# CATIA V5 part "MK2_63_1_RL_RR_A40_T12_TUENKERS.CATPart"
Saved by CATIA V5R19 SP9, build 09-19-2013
Part number: MK2_63_1_RL_RR_A40_T12_TUENKERS
Material "MISCHDICHTE": density 4951.5 kg/m3, Young's modulus 2e+11 Pa, Poisson ratio 0.266
Bounding box of the stored display mesh (mm): x -193.5 to 144, y -121.5 to 73, z -122.161 to 122.161
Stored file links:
  G:\Konstruktion\Modelle\Catia_V5\MK2_63_1_RL_RR_A40_T12_TUENKERS.CATPart
  G:\Konstruktion\Modelle\Catia_V5\Spannarme\SPANNARM_KPL_63_A10_217498_TUENKERS.CATPart
  C:\Catia\Tuenkers_B19SP9HF86_64\win_b64\reffiles\standard\MetricThickPitch.txt
  G:\Konstruktion\Modelle\Catia_V5\Spannarme\SPANNARM_KPL_63_A40_242839_TUENKERS.CATPart
  G:\Konstruktion\Modelle\Catia_V5\MK_63_1_A10_T12_TUENKERS.CATPart
  G:\Konstruktion\Modelle\Catia_V5\V2_63_1_BR3_ZL_ZR_RL_RR_A40_T12_TUENKERS.CATPart
  HANDHEBEL_KPL_50_63_TUENKERS.CATPart
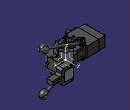
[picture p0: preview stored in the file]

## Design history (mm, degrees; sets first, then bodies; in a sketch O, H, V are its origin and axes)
AxisSystem1: origin (0, 0, 0), X (1, 0, 0), Y (0, 1, 0), Z (0, 0, 1)
Body1 (main body)
  Body2 "*DIT1\\*DIT2\\"
    Solid1: solid without history
  Assemble1: tool Body2
  Body3 "*DIT1\\*DIT3"
    Solid2 "Solid.1": solid without history
  Assemble2: tool Body3
  Body4 "*DIT1\\*DIT12\\*DIT16\\"
    Solid3 "Solid.1": solid without history
  Assemble3: tool Body4
  Body5 "*DIT1\\*DIT12\\*DIT17\\"
    Solid4 "Solid.1": solid without history
  Assemble4: tool Body5
  Body6 "*DIT1\\*DIT12\\MK_MK2_63_1_A10_A11_A12_T12_081112_3D_xSET4_2.1"
    Solid5 "Solid.1": solid without history
    Body7 "*DIT1\\*DIT12\\MK_MK2_63_1_A10_A11_A12_T12_081112_3D_xSET4_2.1\\Body.11 ( *SOL16 - wsp GEHAEUSE -  )"
      Solid6 "Solid.1": solid without history
    Add1 "*DIT1\\*DIT12\\MK_MK2_63_1_A10_A11_A12_T12_081112_3D_xSET4_2.1\\Body.11 ( *SOL16 - wsp GEHAEUSE -  )": tool Body7
    Body8 "*DIT1\\*DIT12\\MK_MK2_63_1_A10_A11_A12_T12_081112_3D_xSET4_2.1\\Body.12 ( *SOL17 - wsp GEHAEUSE -  )"
      Solid7 "Solid.1": solid without history
    Add2 "*DIT1\\*DIT12\\MK_MK2_63_1_A10_A11_A12_T12_081112_3D_xSET4_2.1\\Body.12 ( *SOL17 - wsp GEHAEUSE -  )": tool Body8
    Body9 "*DIT1\\*DIT12\\MK_MK2_63_1_A10_A11_A12_T12_081112_3D_xSET4_2.1\\Body.14 ( *SOL18 - wsp GEHAEUSE -  )"
      Solid8 "Solid.1": solid without history
    Add3 "*DIT1\\*DIT12\\MK_MK2_63_1_A10_A11_A12_T12_081112_3D_xSET4_2.1\\Body.14 ( *SOL18 - wsp GEHAEUSE -  )": tool Body9
  Assemble5: tool Body6
  Body10 "*DIT1\\MK_MK2_63_1_A10_A11_A12_T12_081112_3D_xSET2_1.1"
    Solid9 "Solid.1": solid without history
  Assemble6: tool Body10
  Rotate1: Axis edge [XY plane of AxisSystem1 | ZX plane of AxisSystem1], Angle 90, ToTransfor Assemble6
  Body11
    Body12 "*DIT1\\MK_MK2_63_1_A10_A11_A12_T12_081112_3D_xSET2_1.1\\Body.2 ( *SOL2 - wsp MK_MK2 63_1 -  )"
      Solid10 "Solid.1": solid without history
    Assemble7: tool Body12
    Body13 "*DIT1\\MK_MK2_63_1_A10_A11_A12_T12_081112_3D_xSET2_1.1\\Body.3 ( *SOL3 - wsp MK_MK2 63_1 -  )"
      Solid11 "Solid.1": solid without history
    Assemble8: tool Body13
    Body14 "*DIT1\\MK_MK2_63_1_A10_A11_A12_T12_081112_3D_xSET2_1.1\\Body.4 ( *SOL4 - wsp MK_MK2 63_1 -  )"
      Solid12 "Solid.1": solid without history
    Assemble9: tool Body14
    Body15 "*DIT1\\MK_MK2_63_1_A10_A11_A12_T12_081112_3D_xSET2_1.1\\Body.5 ( *SOL5 - wsp MK_MK2 63_1 -  )"
      Solid13 "Solid.1": solid without history
    Assemble10: tool Body15
    Body16 "*DIT1\\MK_MK2_63_1_A10_A11_A12_T12_081112_3D_xSET2_1.1\\Body.6 ( *SOL6 - wsp MK_MK2 63_1 -  )"
      Solid14 "Solid.1": solid without history
    Assemble11: tool Body16
    Rotate2: Axis edge, Angle 90, ToTransfor Assemble11
    Translate1: Direction edge [YZ plane of AxisSystem1 | XY plane of AxisSystem1], Length -1, ToTransfor Rotate2
  Assemble12: tool Body11
Body17 "Spannarm_kpl_63_A40_242839_Tuenkers", material "Steel"
  Sketch1 on xy-plane, origin (0, 0, 0), H (1, 0, 0), V (0, 1, 0)
    line L1 (73, 144) -> (45, 144)
    arc A1 centre (53, 43.1005) radius 20 from (67.1421, 28.9584) to (73, 43.1005) ccw
    line L2 (67.1421, 28.9584) -> (19.0919, -19.0919)
    line L3 (10.9602, 10.9602) -> (10.9602, -10.9602)
    line L4 (10.9602, 10.9602) -> (-10.9602, 10.9602)
    line L5 (-19.0919, 19.0919) -> (-10.9602, 10.9602)
    line L6 (-1.4396, 36.7442) -> (-19.0919, 19.0919)
    line L7 (38.4202, 51.252) -> (-1.4396, 36.7442)
    arc A2 centre (35, 60.6489) radius 10 from (38.4202, 51.252) to (45, 60.6489) ccw
    line L8 (45, 60.6489) -> (45, 144)
    line L9 (73, 144) -> (73, 43.1005)
    line L10 (10.9602, -10.9602) -> (19.0919, -19.0919)
    point P7 (10.9602, 10.9602)
    point P10 (-1.4396, 36.7442)
    point P13 (73, 37.6447)
    point P14 (45, 51.7188)
    reference intersected line E1 through (0, 0) direction (-0.7071, 0.7071)
    reference intersected line E2 through (0, 0) direction (-0.7071, 0.7071)
    reference intersected line E3 through (0, 0) direction (-0.7071, 0.7071)
    reference intersected line E4 through (0, 0) direction (0, 1) from yz-plane
    reference intersected line E5 through (0, 0) direction (-1, 0) from zx-plane
    reference intersected line E6 through (0, 0) direction (0, 1) from yz-plane
    angle L6 L7 = 25
    radius A1 = 20
    angle L4 L5 = 45
    distance P7 L2 = 27
    distance L2 L6 = 54
    angle L2 L10 = 90
    distance P7 E1 = 15.5
    distance E4 L3 = 10.9602
    distance E5 L1 = 144
    distance E6 L8 = 45
    distance L9 L8 = 28
    radius A2 = 10
    distance P10 L1 = 107.2558
    tangency: A1 L2, L8 A2, A2 L7, L9 A1
    coincidence: L10 E2, L5 E3
  Pad1: profile Sketch1, direction (0, 0, 1), length 39, opposite side length 39
  Chamfer1: length 0.1, angle 45, on edge [face of Pad1 from Sketch1.L3 | end face of Pad1]; edge [face of Pad1 from Sketch1.L4 | end face of Pad1]; edge [start face of Pad1 | face of Pad1 from Sketch1.L4]; edge [start face of Pad1 | face of Pad1 from Sketch1.L3]
  Sketch2 on face of Pad1 from Sketch1.L9, origin (73, 0, 0), H (0, 1, 0), V (0, 0, 1)
    line L1 (144, -10) -> (144, 10)
    line L2 (103, 10) -> (144, 10)
    arc A1 centre (103, 18) radius 8 from (103, 10) to (95, 18) cw
    line L3 (95, 18) -> (95, 29)
    arc A2 centre (85, 29) radius 10 from (85, 39) to (95, 29) cw
    line L4 (-20, 39) -> (85, 39)
    line L5 (-20, 39) -> (-20, 27)
    line L6 (74, 27) -> (-20, 27)
    arc A3 centre (74, 21) radius 6 from (74, 27) to (80, 21) cw
    line L7 (80, 21) -> (80, -21)
    arc A4 centre (74, -21) radius 6 from (80, -21) to (74, -27) cw
    line L8 (-20, -27) -> (74, -27)
    line L9 (-20, -27) -> (-20, -39)
    line L10 (-20, -39) -> (85, -39)
    arc A5 centre (85, -29) radius 10 from (95, -29) to (85, -39) cw
    line L11 (95, -29) -> (95, -18)
    arc A6 centre (103, -18) radius 8 from (95, -18) to (103, -10) cw
    line L12 (103, -10) -> (144, -10)
    reference intersected line E1 through (0, 0) direction (-1, 0) from xy-plane
    reference intersected line E2 through (0, 0) direction (0, 1) from zx-plane
    reference intersected line E3 through (0, 0) direction (0, 1) from zx-plane
    reference intersected line E4 through (0, 0) direction (0, 1) from zx-plane
    line L13 (-30, -44) -> (160, -44)
    line L14 (160, -44) -> (160, 44)
    line L15 (160, 44) -> (-30, 44)
    line L16 (-30, 44) -> (-30, -44)
    reference intersected line E5 through (0, 0) direction (-1, 0) from xy-plane
    reference intersected line E6 through (0, 0) direction (0, 1) from zx-plane
    distance L12 E1 = 10
    distance L12 L2 = 20
    distance L4 L10 = 78
    distance L6 L8 = 54
    distance L10 L12 = 29
    distance L8 L10 = 12
    radius A3 = 6
    radius A4 = 6
    radius A5 = 10
    radius A2 = 10
    radius A1 = 8
    radius A6 = 8
    distance L7 E2 = 80
    distance L3 E3 = 95
    distance L1 L5 = 164
    distance E4 L1 = 144
    distance L16 L14 = 190
    distance L15 L13 = 88
    distance L13 E5 = 44
    distance L14 E6 = 160
    tangency: L6 A3, A3 L7, L7 A4, A4 L8, L10 A5, A5 L11, L3 A1, A1 L2, A6 L12, A2 L4, A2 L3, A6 L11
    vertical: L1 V, L14 V, L16 V
    horizontal: L12 H, L13 H, L15 H
    coincidence: L5 L9, L11 L3
  Pocket1: profile Sketch2, direction (-1, 0, 0), length 95
  Sketch3 on face of Pad1 from Sketch1.L9, origin (73, 131.0889, -0.3784), H (0, 1, 0), V (0, 0, 1)
    point P1 (3.9111, 0.3784)
    reference intersected line E1 through (0, 0.3784) direction (-1, 0) from xy-plane
    reference intersected line E2 through (-131.0889, 0) direction (0, 1) from zx-plane
    reference intersected line E3 through (-131.0889, 0) direction (0, 1) from zx-plane
    reference intersected line E4 (12.9111, -38.6216) -> (-87.9884, -38.6216) from start face of Pad1
    distance P1 E2 = 135
    distance E3 E4 = 0
    coincidence: P1 E1
  Hole1: placed by Sketch3, at (73, 135, 0) direction (-1, 0, 0), diameter 6, through (limit type 6)
  Sketch4 on face of Pad1 from Sketch1.L9, origin (73, 113.9529, 0.5693), H (0, 1, 0), V (0, 0, 1)
    point P1 (-8.9529, -0.5693)
    reference projected point E1 (21.0471, -0.5693) from axis of face of Hole1
    reference intersected line E2 through (0, -0.5693) direction (-1, 0) from xy-plane
    distance P1 E1 = 30
    coincidence: P1 E2
  Hole2: placed by Sketch4, at (73, 105, 0) direction (-1, 0, 0), diameter 6, through (limit type 6)
  Sketch5 on face of Pad1 from Sketch1.L9, origin (73, 123.4122, -0.1089), H (0, 1, 0), V (0, 0, 1)
    point P1 (-3.4122, 0.1089)
    reference projected point E1 (11.5878, 0.1089) from axis of face of Hole1
    reference projected point E2 (-18.4122, 0.1089) from axis of face of Hole2
    distance P1 E1 = 15
    distance E2 P1 = 15
  Hole3: placed by Sketch5, at (73, 120, 0) direction (-1, 0, 0), diameter 9, through (limit type 6)
  Sketch6 on face of Pad1 from Sketch1.L9, origin (73, 93.5248, 1.4062), H (0, 1, 0), V (0, 0, 1)
    point P1 (-3.5248, -1.4062)
    reference projected point E1 (26.4752, -1.4062) from axis of face of Hole3
    reference projected point E2 (11.4752, -1.4062) from axis of face of Hole2
    distance P1 E1 = 30
    distance P1 E2 = 15
  Hole4: placed by Sketch6, at (73, 90, 0) direction (-1, 0, 0), diameter 9, through (limit type 6)
  Sketch7 on face of Pad1 from Sketch1.L10, origin (13.7879, -13.7879, 28.7565), H (0.7071, -0.7071, 0), V (0, 0, 1)
    point P1 (0.5009, 4.2435)
    reference intersected line E1 through (0, -28.7565) direction (-1, 0) from xy-plane
    reference projected line E2 (-19.4991, -67.7565) -> (-19.4991, 10.2435) from edge [face of Pad1 from Sketch1.L3 | face of Pad1 from Sketch1.L4]
    distance P1 E1 = 33
    distance E2 P1 = 20
  Hole5: placed by Sketch7, at (14.1421, -14.1421, 33) direction (0.7071, 0.7071, 0), diameter 6.647, depth 18, V-bottom angle 120, threaded "M8", thread diameter 8, thread depth 15, pitch 1.25
  RectPattern1: of Hole5, direction 1 instances 2, spacing 66, along edge [face of Pad1 from Sketch1.L3 | face of Pad1 from Sketch1.L4] reversed, direction 2 instances 2, spacing 40, along edge [face of Pad1 from Sketch1.L10 | face of Pocket1] reversed
  Body18 "KLEMMFLANSCH KPL"
    Sketch8 on xy-plane, origin (0, 0, 0), H (1, 0, 0), V (0, 1, 0)
      line L1 (-20.5061, 17.6777) -> (-31.1375, 7.0463)
      line L2 (-31.1375, 7.0463) -> (-19.1167, -4.9745)
      line L3 (-19.1167, -4.9745) -> (-25.4806, -11.3385)
      line L4 (-25.4806, -11.3385) -> (-11.3385, -25.4806)
      line L5 (-11.3385, -25.4806) -> (-4.9745, -19.1167)
      line L6 (-4.9745, -19.1167) -> (7.0463, -31.1375)
      line L7 (7.0463, -31.1375) -> (19.0671, -19.1167)
      line L8 (19.0671, -19.1167) -> (10.9106, -10.9602)
      line L9 (10.9106, -10.9602) -> (-10.9602, -10.9602)
      point P10 (-10.9602, -10.9602)
      line L10 (-10.9602, -10.9602) -> (-10.9602, 8.1317)
      line L11 (-10.9602, 8.1317) -> (-20.5061, 17.6777)
      reference intersected line E1 through (0, 0) direction (-0.7071, 0.7071)
      reference intersected line E2 through (0, 0) direction (-0.7071, 0.7071)
      reference intersected line E3 through (0, 0) direction (-0.7071, -0.7071)
      distance L4 L8 = 26
      distance L7 L5 = 17
      distance L5 L3 = 20
      distance L7 L1 = 54
      distance L4 L6 = 9
      distance E1 P10 = 15.5
      distance L11 E2 = 2
      distance L11 L8 = 1.965
      angle L11 L10 = 135
      angle L9 L8 = 45
      distance L7 P10 = 27
      distance E3 L7 = 27
      coincidence: L2 L6
    Pad2: profile Sketch8, direction (0, 0, 1), length 39, opposite side length -27
    Chamfer2: length 0.1, angle 45, on edge [face of Pad2 from Sketch8.L9 | end face of Pad2]; edge [face of Pad2 from Sketch8.L10 | end face of Pad2]
    Sketch9 on face of Pad2 from Sketch8.L6, origin (-12.0456, -12.0456, 0), H (0.7071, -0.7071, 0), V (0, 0, 1)
      circle A1 centre (20, 33) radius 4
      point P1 (20, 33)
      circle A2 centre (-20, 33) radius 4
      point P2 (-20, 33)
      reference projected line E1 (-27, 27) -> (-10, 27) from edge [start face of Pad2 | face of Pad2 from Sketch8.L2]
      reference projected line E2 (10, 27) -> (27, 27) from edge [start face of Pad2 | face of Pad2 from Sketch8.L6]
      reference projected line E3 (27, 27) -> (27, 39) from edge [face of Pad2 from Sketch8.L7 | face of Pad2 from Sketch8.L6]
      reference projected line E4 (-27, 27) -> (-27, 39) from edge [face of Pad2 from Sketch8.L2 | face of Pad2 from Sketch8.L1]
      radius A1 = 4
      radius A2 = 4
      distance E1 P2 = 6
      distance P1 E2 = 6
      distance E3 P1 = 7
      distance P2 E4 = 7
    Pad3: profile Sketch9, direction (0.7071, 0.7071, 0), length 20
    Sketch10 on face of Pad3, origin (-12.0456, -12.0456, 0), H (0.7071, -0.7071, 0), V (0, 0, 1)
      circle A1 centre (20, 33) radius 6.5
      point P1 (20, 33)
      circle A2 centre (-20, 33) radius 6.5
      point P2 (-20, 33)
      reference projected line E1 (-27, 27) -> (-27, 39) from edge [face of Pad2 from Sketch8.L2 | face of Pad2 from Sketch8.L1]
      reference projected line E2 (27, 27) -> (27, 39) from edge [face of Pad2 from Sketch8.L7 | face of Pad2 from Sketch8.L6]
      reference projected line E3 (-27, 27) -> (-10, 27) from edge [start face of Pad2 | face of Pad2 from Sketch8.L2]
      reference projected line E4 (10, 27) -> (27, 27) from edge [start face of Pad2 | face of Pad2 from Sketch8.L6]
      radius A1 = 6.5
      radius A2 = 6.5
      distance E1 P2 = 7
      distance E2 P1 = 7
      distance E3 P2 = 6
      distance E4 P1 = 6
    Pad4: profile Sketch10, direction (-0.7071, -0.7071, 0), length 1.4
    Chamfer3: length 0.1, angle 45, on edge [face of Pad4 from Sketch10.A1 | end face of Pad4]; edge [face of Pad4 from Sketch10.A2 | end face of Pad4]
    Sketch11 on end face of Pad4, origin (-13.0355, -13.0355, 0), H (0.7071, -0.7071, 0), V (0, 0, 1)
      circle A1 centre (20, 33) radius 6.5
      point P1 (20, 33)
      circle A2 centre (-20, 33) radius 6.5
      point P2 (-20, 33)
      reference projected line E1 (10, 27) -> (27, 27) from edge [start face of Pad2 | face of Pad3]
      reference projected line E2 (27, 27) -> (27, 39) from edge [face of Pad2 from Sketch8.L7 | face of Pad2 from Sketch8.L6]
      reference projected line E3 (-27, 27) -> (-27, 39) from edge [face of Pad2 from Sketch8.L2 | face of Pad2 from Sketch8.L1]
      reference projected line E4 (-27, 27) -> (-10, 27) from edge [start face of Pad2 | face of Pad3]
      radius A1 = 6.5
      radius A2 = 6.5
      distance E1 P1 = 6
      distance E2 P1 = 7
      distance E3 P2 = 7
      distance E4 P2 = 6
    Pad5: profile Sketch11, direction (-0.7071, -0.7071, 0), length 8
    Fillet1: radius 0.5, on end face of Pad5; edge [face of Pad5 from Sketch11.A1 | end face of Pad5]
    Mirror1: of the body so far, about xy-plane, deactivated
    Translate2: Direction edge [ZX plane of AxisSystem1 | YZ plane of AxisSystem1], Length -66, ToTransfor Mirror1
  Assemble13: tool Body18
  Rotate3: Axis edge [XY plane of AxisSystem1 | ZX plane of AxisSystem1], Angle 180, ToTransfor Assemble13
  Rotate4: Axis edge [ZX plane of AxisSystem1 | YZ plane of AxisSystem1], Angle 90, ToTransfor Rotate3
Body19 "ENDLAGENRASTE_LINKS"
  Solid15 "Manifold Solid #1213": solid without history
  Body20 "LUMP70"
    Solid16 "Manifold Solid #2778": solid without history
  Assemble14: tool Body20
  Body21 "LUMP73"
    Solid17 "Manifold Solid #4455": solid without history
  Assemble15: tool Body21
  Body22 "LUMP74"
    Solid18 "Manifold Solid #5598": solid without history
  Assemble16: tool Body22
  Body23 "LUMP76"
    Solid19 "Manifold Solid #7126": solid without history
  Assemble17: tool Body23
  Body24 "LUMP79"
    Solid20 "Manifold Solid #8329": solid without history
  Assemble18: tool Body24
  Body25 "LUMP81"
    Solid21 "Manifold Solid #8843": solid without history
  Assemble19: tool Body25
  Body26 "LUMP82"
    Solid22 "Manifold Solid #9252": solid without history
  Assemble20: tool Body26
  Body27 "LUMP85"
    Solid23 "Manifold Solid #10175": solid without history
  Assemble21: tool Body27
  Body28 "LUMP87"
    Solid24 "Manifold Solid #10993": solid without history
  Assemble22: tool Body28
  Body29 "LUMP88"
    Solid25 "Manifold Solid #11378": solid without history
  Assemble23: tool Body29
  Body30 "LUMP89"
    Solid26 "Manifold Solid #12146": solid without history
  Assemble24: tool Body30, deactivated
  Body31 "LUMP93"
    Solid27 "Manifold Solid #13965": solid without history
  Assemble25: tool Body31, deactivated
  Body32 "LUMP94"
    Solid28 "Manifold Solid #14222": solid without history
  Assemble26: tool Body32, deactivated
  Body33 "LUMP97"
    Solid29 "Manifold Solid #15145": solid without history
  Assemble27: tool Body33, deactivated
  Body34 "LUMP98"
    Solid30 "Manifold Solid #15554": solid without history
  Assemble28: tool Body34, deactivated
  Body35 "LUMP101"
    Solid31 "Manifold Solid #16781": solid without history
  Assemble29: tool Body35
  Body36 "LUMP102"
    Solid32 "Manifold Solid #17038": solid without history
  Assemble30: tool Body36
  Rotate5: Axis edge, Angle 90, ToTransfor Assemble30
Body37 "ENDLAGENRASTE_RECHTS"
  Body38 "LUMP69"
    Solid33 "Manifold Solid #2521": solid without history
  Assemble31: tool Body38
  Body39 "LUMP71"
    Solid34 "Manifold Solid #3035": solid without history
  Assemble32: tool Body39
  Body40 "LUMP72"
    Solid35 "Manifold Solid #3745": solid without history
  Assemble33: tool Body40
  Body41 "LUMP75"
    Solid36 "Manifold Solid #6741": solid without history
  Assemble34: tool Body41
  Body42 "LUMP77"
    Solid37 "Manifold Solid #7511": solid without history
  Assemble35: tool Body42
  Body43 "LUMP78"
    Solid38 "Manifold Solid #7920": solid without history
  Assemble36: tool Body43
  Body44 "LUMP80"
    Solid39 "Manifold Solid #8586": solid without history
  Assemble37: tool Body44
  Body45 "LUMP83"
    Solid40 "Manifold Solid #9661": solid without history
  Assemble38: tool Body45
  Body46 "LUMP84"
    Solid41 "Manifold Solid #9918": solid without history
  Assemble39: tool Body46
  Body47 "LUMP86"
    Solid42 "Manifold Solid #10584": solid without history
  Assemble40: tool Body47
  Body48 "LUMP90"
    Solid43 "Manifold Solid #12531": solid without history
  Assemble41: tool Body48
  Body49 "LUMP91"
    Solid44 "Manifold Solid #13299": solid without history
  Assemble42: tool Body49
  Body50 "LUMP92"
    Solid45 "Manifold Solid #13708": solid without history
  Assemble43: tool Body50
  Body51 "LUMP95"
    Solid46 "Manifold Solid #14479": solid without history
    Translate3: Direction edge [face of Solid44 | face of Solid44], Length -4, ToTransfor Solid46
  Assemble44: tool Body51
  Body52 "LUMP96"
    Solid47 "Manifold Solid #14736": solid without history
    Translate4: Direction edge [face of Solid44 | face of Solid44], Length -4, ToTransfor Solid47
  Assemble45: tool Body52
  Body53 "LUMP99"
    Solid48 "Manifold Solid #15963": solid without history
    Translate5: Direction edge [face of Solid44 | face of Solid44], Length -4, ToTransfor Solid48
  Assemble46: tool Body53
  Body54 "LUMP100"
    Solid49 "Manifold Solid #16372": solid without history
    Translate6: Direction edge [face of Solid44 | face of Solid44], Length -4, ToTransfor Solid49
  Assemble47: tool Body54
  Body55 "LUMP103"
    Solid50 "Manifold Solid #17295": solid without history
  Assemble48: tool Body55
  Rotate6: Axis edge, Angle 90, ToTransfor Assemble48
Body56 "Handhebel_KPL_218625_TUENKERS.1"
  Solid51: solid without history
  Body57 "Handhebel_KPL_218625_TUENKERS.2"
    Solid52: solid without history
  Assemble49: tool Body57
  Translate7: Direction edge [ZX plane of AxisSystem1 | YZ plane of AxisSystem1], ToTransfor Assemble49, Length 28
  Translate8: Direction edge [XY plane of AxisSystem1 | ZX plane of AxisSystem1], ToTransfor Translate7, Length -86
  Translate9: Direction edge [YZ plane of AxisSystem1 | XY plane of AxisSystem1], ToTransfor Translate8, Length -4
Body58 "Handhebel_KPL_218625_TUENKERS.1"
  Solid53: solid without history
  Body59 "Handhebel_KPL_218625_TUENKERS.2"
    Solid54: solid without history
  Assemble50: tool Body59
  Translate10: Direction edge [ZX plane of AxisSystem1 | YZ plane of AxisSystem1], Length 28, ToTransfor Assemble50
  Translate11: Direction edge [XY plane of AxisSystem1 | ZX plane of AxisSystem1], Length -86, ToTransfor Translate10
  Translate12: Direction edge [YZ plane of AxisSystem1 | XY plane of AxisSystem1], Length -4, ToTransfor Translate11
  Symmetry1: ToTransfor Translate12, Reference XY plane of AxisSystem1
